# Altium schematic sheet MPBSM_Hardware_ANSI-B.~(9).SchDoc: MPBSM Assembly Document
size 431 x 279 mm; Date: Not shown in title block; ApprovedBy: Not shown in title block; CheckedBy: Not shown in title block; Author: Not shown in title block; CompanyName: Not shown in title block; Engineer: Not shown in title block; Organization: Not shown in title block; Address1: Not shown in title block; Address2: Not shown in title block; Address3: Not shown in title block; Address4: Not shown in title block; DocumentNumber: 12; Revision: Use project parameter SCH_Rev; SheetNumber: 12; SheetTotal: 12; PageSetup: Record=PageOptions¦CenterHorizontal=True¦CenterVertical=True¦PrintScale=1.00¦XCorrection=1.00¦YCorrection=1.00¦PrintKind=0¦BorderSize=5000000¦LeftOffset=0¦BottomOffset=0¦Orientation=2¦PaperLength=1000¦PaperWidth=1000¦Scale=100¦PaperSource=15¦PrintQuality=600¦MediaType=1¦DitherType=10¦PaperKind=Letter¦PrintScaleMode=1
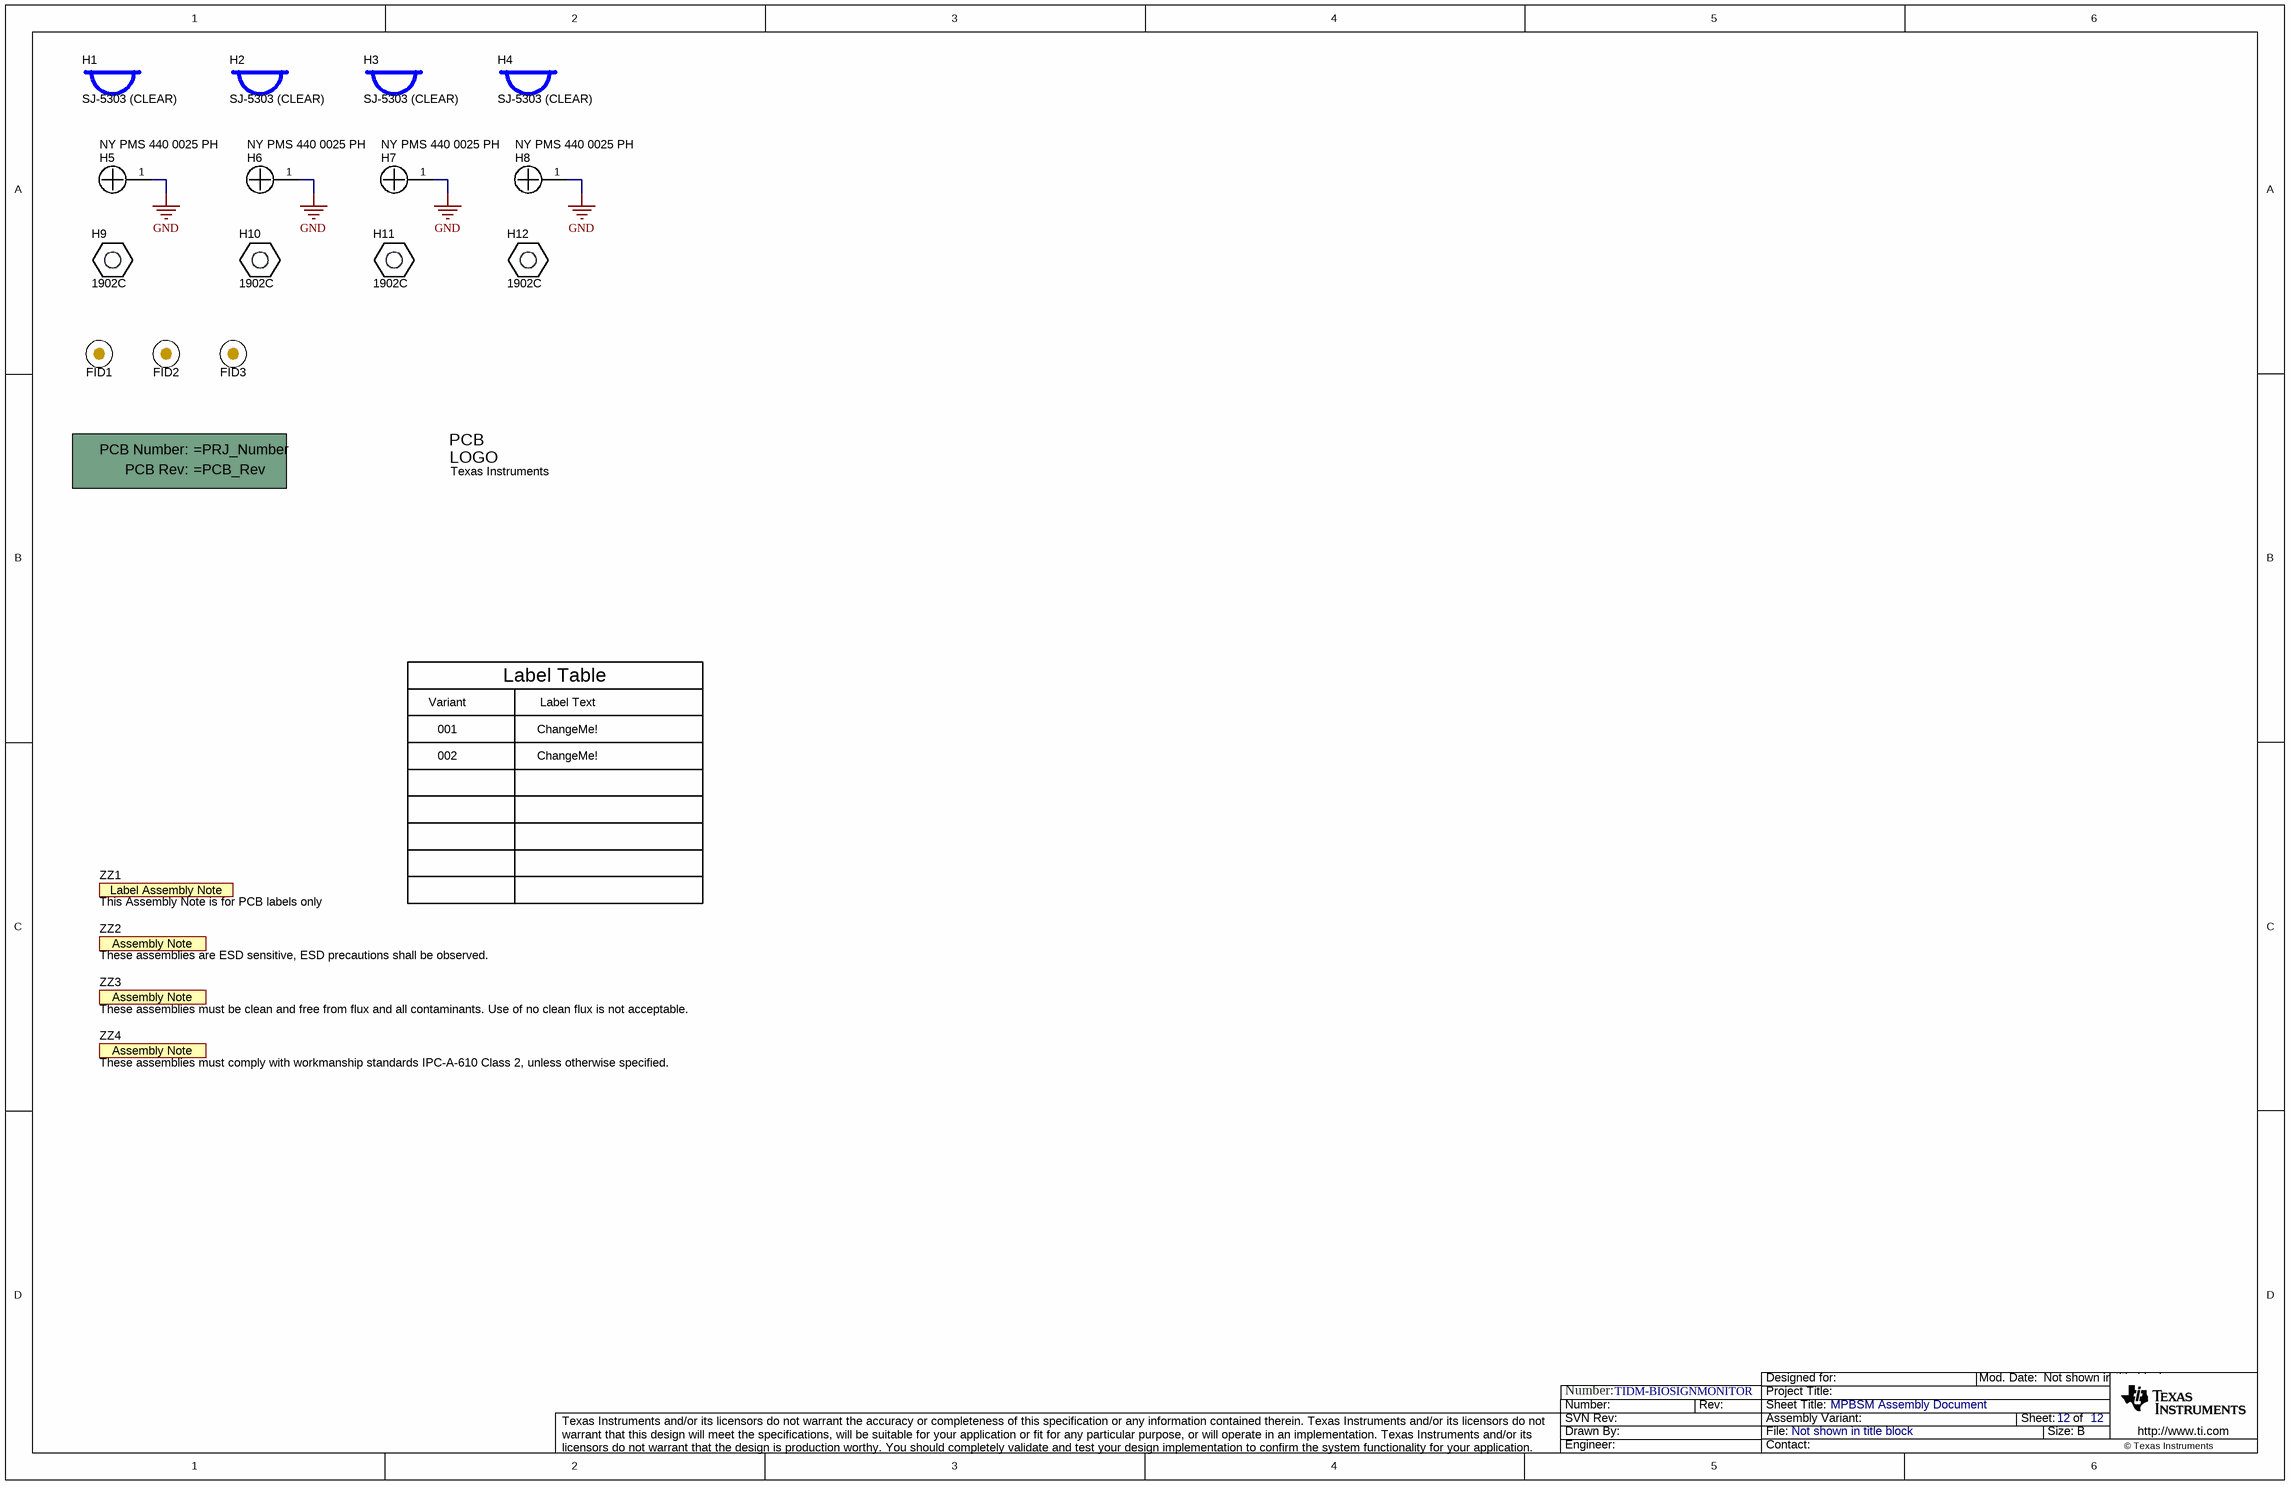
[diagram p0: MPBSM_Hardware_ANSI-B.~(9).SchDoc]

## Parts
!PCB1  Printed Circuit Board  (value not drawn)  (mechanical)
FID1  Fiducial  [Fiducial10-20]  (value not drawn)
FID2  Fiducial  [Fiducial10-20]  (value not drawn)
FID3  Fiducial  [Fiducial10-20]  (value not drawn)
H1  SJ-5303 (CLEAR)  [Bumpon_SJ5003Transparent]
H2  SJ-5303 (CLEAR)  [Bumpon_SJ5003Transparent]
H3  SJ-5303 (CLEAR)  [Bumpon_SJ5003Transparent]
H4  SJ-5303 (CLEAR)  [Bumpon_SJ5003Transparent]
H5  NY PMS 440 0025 PH  [NY PMS 440 0025 PH]
H6  NY PMS 440 0025 PH  [NY PMS 440 0025 PH]
H7  NY PMS 440 0025 PH  [NY PMS 440 0025 PH]
H8  NY PMS 440 0025 PH  [NY PMS 440 0025 PH]
H9  1902C  [Keystone_1902C]
H10  1902C  [Keystone_1902C]
H11  1902C  [Keystone_1902C]
H12  1902C  [Keystone_1902C]
Logo1  Texas Instruments  [TI_Symbol_Overlay_Small]  (no BOM)
ZZ1  This Assembly Note is for PCB labels only  [AssemblyNoteLabel]  (no BOM)
ZZ2  These assemblies are ESD sensitive, ESD precautions shall be observed.  [AssemblyNote]  (no BOM)
ZZ3  These assemblies must be clean and free from flux and all contaminants. Use of no clean flux is not acceptable.  [AssemblyNote]  (no BOM)
ZZ4  These assemblies must comply with workmanship standards IPC-A-610 Class 2, unless otherwise specified.  [AssemblyNote]  (no BOM)

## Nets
GND: H5.1 H6.1 H7.1 H8.1

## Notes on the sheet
- Variant
- Label Table
- Label Text
- 001
- 002
- ChangeMe!
- Number:
- TIDM-BIOSIGNMONITOR

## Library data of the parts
!PCB1 = PCB: Manufacturer: Any; SymbolCreator: a0412235
FID1-FID3 = Fiducial: Fiducial mark.  There is nothing to buy or mount.; SymbolCreator: codlsc
H1-H4 = SJ-5303 (CLEAR): Bumpon, Hemisphere, 0.44 X 0.20, Clear; Manufacturer: 3M; SymbolCreator: a0412235
H5-H8 = NY PMS 440 0025 PH: Machine Screw, Round, #4-40 x 1/4, Nylon, Philips panhead; Manufacturer: B&F Fastener Supply; CompType: Hardware; SymbolCreator: codlsc; U/M: EA
H9-H12 = 1902C: Standoff, Hex, 0.5"L #4-40 Nylon; Manufacturer: Keystone; CompType: Hardware
Logo1 = TI_Logo: Texas Instrument Corporate Signature; SymbolCreator: codlsc
ZZ1 = AssemblyNoteLabel: SymbolCreator: a0412235
ZZ2-ZZ4 = AssemblyNote: SymbolCreator: codlsc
